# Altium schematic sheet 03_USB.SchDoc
size A2; ApprovedBy: DNP; CheckedBy: DNP; Author: DNP; CompanyName: Google LLC; DrawnBy: DNP; Engineer: Bangfei/Michael/Leo; Organization: Google LLC; Address1: 1600 Amphitheatre Parkway; Address2: Mountain View, CA 94043; Address3: DNP; Address4: DNP; DocumentNumber: DNP; Revision: PVT; SheetNumber: 3; SheetTotal: 11; VersionControl_RevNumber: DNP; IsUserConfigurable: DNP
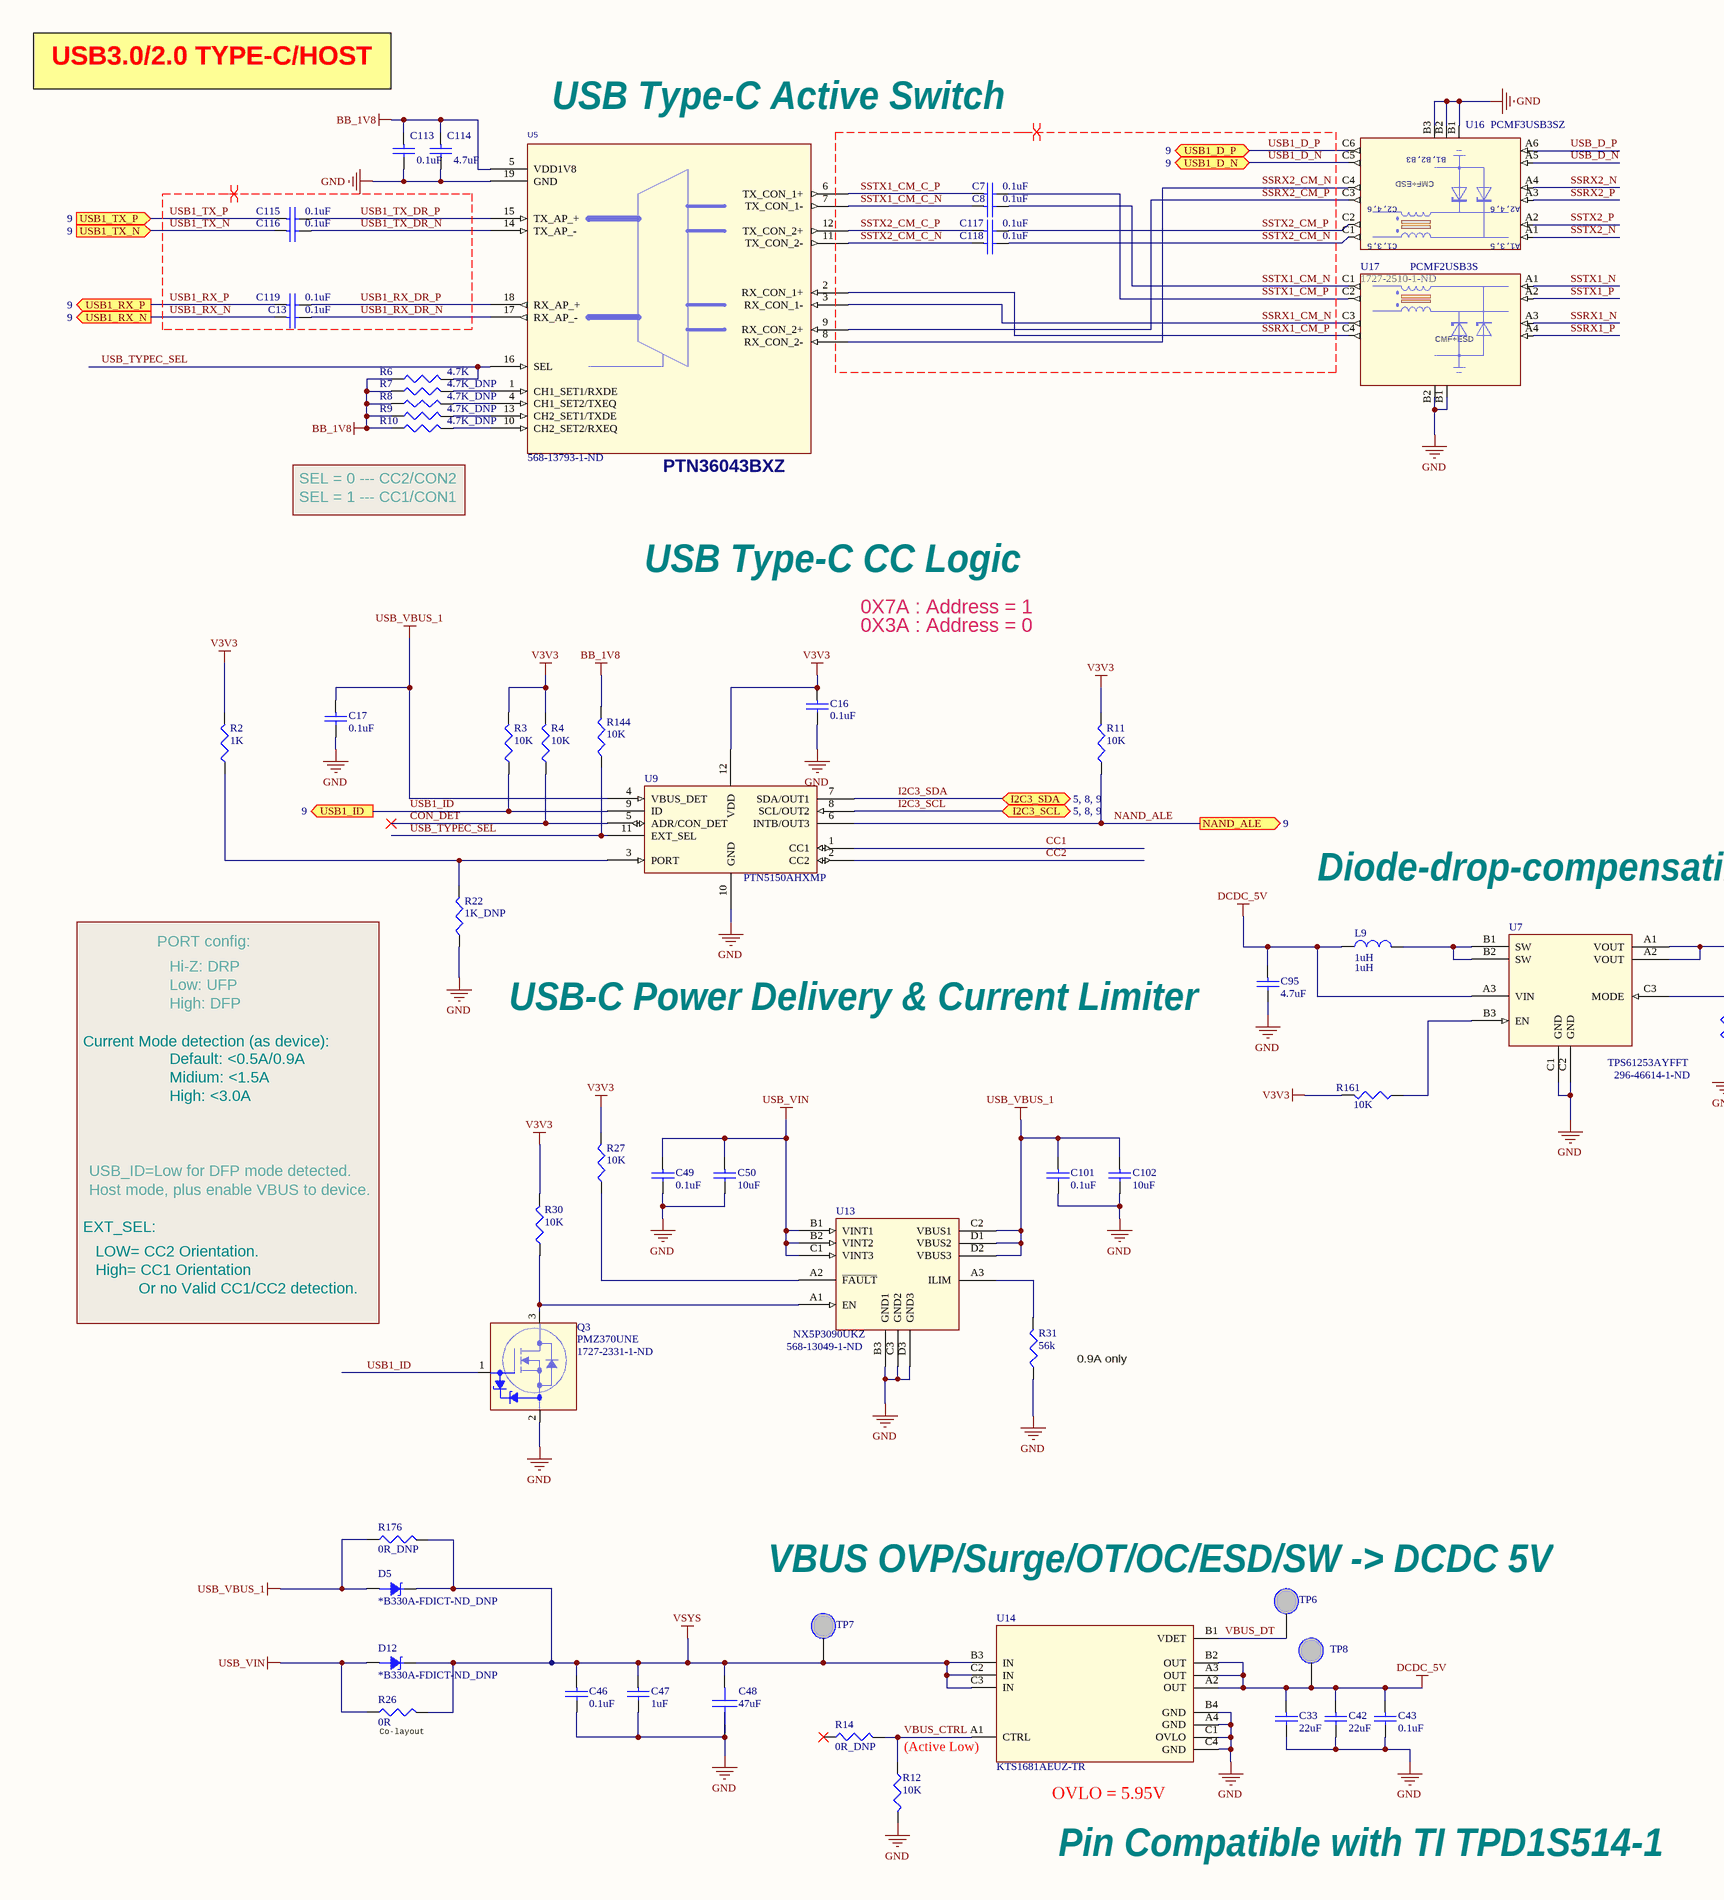
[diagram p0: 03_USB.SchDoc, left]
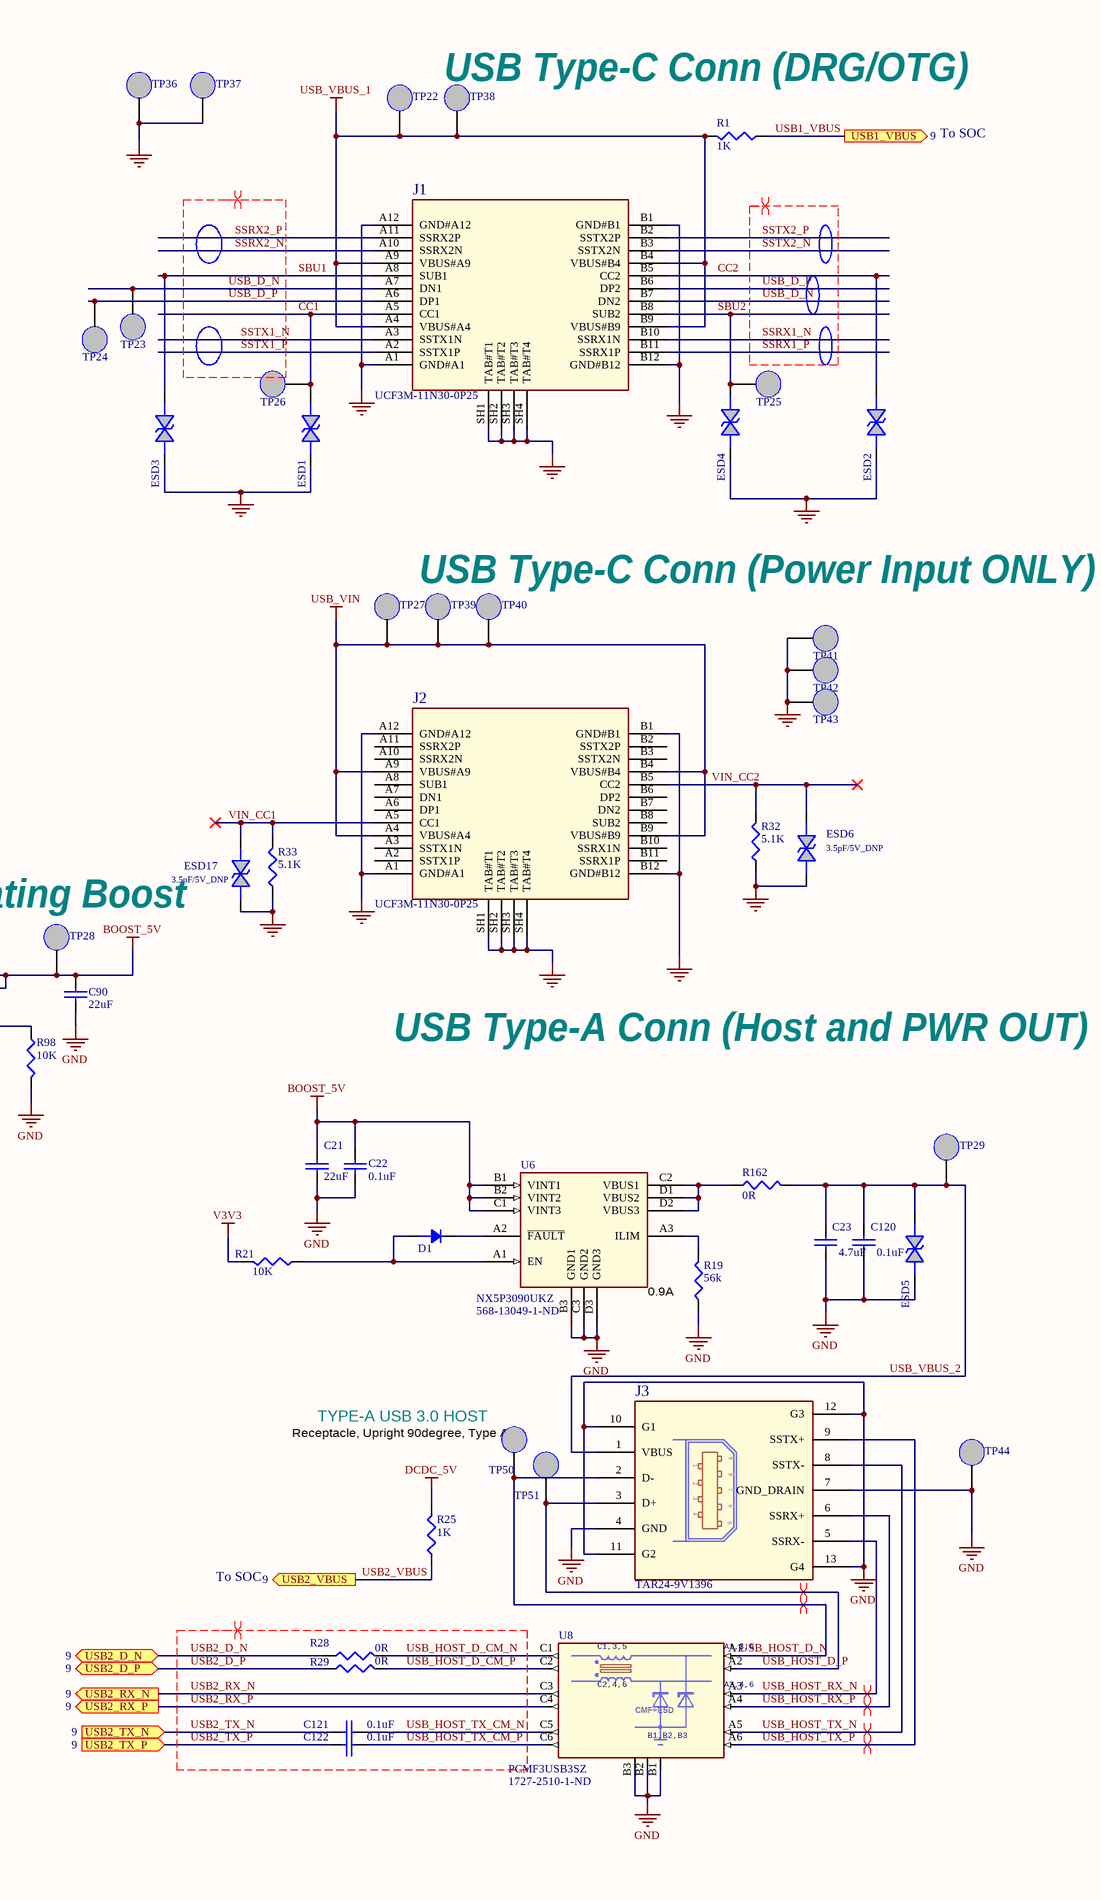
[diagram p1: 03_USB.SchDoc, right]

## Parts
C7  value 0.1uF  [0201]  (hidden comment: 0.1uF/10V)
C8  value 0.1uF  [0201]  (hidden comment: 0.1uF/10V)
C13  value 0.1uF  [0201]  (hidden comment: 0.1uF/10V)
C16  value 0.1uF  [0402]  (hidden comment: 0.1uF/25V)
C17  value 0.1uF  [0402]  (hidden comment: 0.1uF/25V)
C21  value 22uF  [0603]  (hidden comment: 22uF/10V)
C22  value 0.1uF  [0201]  (hidden comment: 0.1uF/10V)
C23  value 4.7uF  [0603]  (hidden comment: 4.7uF/10V)
C33  value 22uF  [0603]  (hidden comment: 22uF/10V)
C42  value 22uF  [0603]  (hidden comment: 22uF/10V)
C43  value 0.1uF  [0201]  (hidden comment: 0.1uF/10V)
C46  value 0.1uF  [0402]  (hidden comment: 0.1uF/25V)
C47  value 1uF  [0402]  (hidden comment: 1uF/25V)
C48  value 47uF  [1206]  (hidden comment: 47uF/25V)
C49  value 0.1uF  [0402]  (hidden comment: 0.1uF/25V)
C50  value 10uF  [0402]  (hidden comment: 10uF/10V)
C90  value 22uF  [0603]  (hidden comment: 10uF/10V)
C95  value 4.7uF  [0603]  (hidden comment: 4.7uF/10V)
C101  value 0.1uF  [0402]  (hidden comment: 0.1uF/25V)
C102  value 10uF  [0402]  (hidden comment: 10uF/10V)
C113  value 0.1uF  [0201]  (hidden comment: 0.1uF/10V)
C114  value 4.7uF  [0402]  (hidden comment: 4.7uF/10V)
C115  value 0.1uF  [0201]  (hidden comment: 0.1uF/10V)
C116  value 0.1uF  [0201]  (hidden comment: 0.1uF/10V)
C117  value 0.1uF  [0201]  (hidden comment: 0.1uF/10V)
C118  value 0.1uF  [0201]  (hidden comment: 0.1uF/10V)
C119  value 0.1uF  [0201]  (hidden comment: 0.1uF/10V)
C120  value 0.1uF  [0201]  (hidden comment: 0.1uF/10V)
C121  value 0.1uF  [0201]  (hidden comment: 0.1uF/10V)
C122  value 0.1uF  [0201]  (hidden comment: 0.1uF/10V)
D1  CUS10F30  [0805-Diode]  (value not drawn)
D5  Supplier Part Number 1: *B330A-FDICT-ND_DNP  [SMA-Diode]  (hidden comment: B330A-FDICT-ND_DNP)
D12  Supplier Part Number 1: *B330A-FDICT-ND_DNP  [SMA-Diode]  (hidden comment: B330A-FDICT-ND_DNP)
ESD1  3.5pF/5V  [0201]  (value not drawn)
ESD2  3.5pF/5V  [0201]  (value not drawn)
ESD3  3.5pF/5V  [0201]  (value not drawn)
ESD4  3.5pF/5V  [0201]  (value not drawn)
ESD5  3.5pF/5V  [0201]  (value not drawn)
ESD6  3.5pF/5V_DNP  [0201]
ESD17  3.5pF/5V_DNP  [0201]
J1  UCF3M-11N30-0P25  [USB12_0_5-UCF3M-11N30-0P25]
J2  UCF3M-11N30-0P25  [USB12_0_5-UCF3M-11N30-0P25]
J3  TAR24-9V1396  [USB9-3_0-TAR24-9V1396]
L9  1uH  [INDC2016X12L]
Q3  PMZ370UNE  Supplier Part Number 1: 1727-2331-1-ND  [DFN10106B]
R1  value 1K  [0201]  (hidden comment: 1K/1%)
R2  value 1K  [0201]  (hidden comment: 1K/1%)
R3  10K  [0201]
R4  10K  [0201]
R6  4.7K  [0201]
R7  value 4.7K_DNP  [0201]  (hidden comment: 4.7K)
R8  value 4.7K_DNP  [0201]  (hidden comment: 4.7K)
R9  value 4.7K_DNP  [0201]  (hidden comment: 4.7K)
R10  value 4.7K_DNP  [0201]  (hidden comment: 4.7K)
R11  10K  [0201]
R12  10K  [0201]
R14  0R_DNP  [0201]
R19  56k  [0402]
R21  10K  [0201]
R22  1K_DNP  [0201]
R25  value 1K  [0201]  (hidden comment: 1K/1%)
R26  0R  [1206]
R27  10K  [0201]
R28  0R  [0201]
R29  0R  [0201]
R30  10K  [0201]
R31  56k  [0402]
R32  5.1K  [0201]
R33  5.1K  [0201]
R98  10K  [0201]
R144  10K  [0201]
R161  10K  [0201]
R162  0R  [0402]
R176  value 0R_DNP  [1206]  (hidden comment: 0R)
TP6  TP NM  [TP_SMD_L]  (value not drawn)  (no BOM)
TP7  TP NM  [TP_SMD_L]  (value not drawn)  (no BOM)
TP8  TP NM  [TP_SMD_L]  (value not drawn)  (no BOM)
TP22  TP NM  [TP_SMD_L]  (value not drawn)  (no BOM)
TP23  TP NM  [TP_SMD]  (value not drawn)  (no BOM)
TP24  TP NM  [TP_SMD]  (value not drawn)  (no BOM)
TP25  TP NM  [TP_SMD]  (value not drawn)  (no BOM)
TP26  TP NM  [TP_SMD]  (value not drawn)  (no BOM)
TP27  TP NM  [TP_SMD_L]  (value not drawn)  (no BOM)
TP28  TP NM  [TP_SMD_L]  (value not drawn)  (no BOM)
TP29  TP NM  [TP_SMD_L]  (value not drawn)  (no BOM)
TP36  TP NM  [TP_SMD_L]  (value not drawn)  (no BOM)
TP37  TP NM  [TP_SMD_L]  (value not drawn)  (no BOM)
TP38  TP NM  [TP_SMD_L]  (value not drawn)  (no BOM)
TP39  TP NM  [TP_SMD_L]  (value not drawn)  (no BOM)
TP40  TP NM  [TP_SMD_L]  (value not drawn)  (no BOM)
TP41  TP NM  [TP_SMD_L]  (value not drawn)  (no BOM)
TP42  TP NM  [TP_SMD_L]  (value not drawn)  (no BOM)
TP43  TP NM  [TP_SMD_L]  (value not drawn)  (no BOM)
TP44  TP NM  [TP_SMD_L]  (value not drawn)  (no BOM)
TP50  TP NM  [TP_SMD_L]  (value not drawn)  (no BOM)
TP51  TP NM  [TP_SMD_L]  (value not drawn)  (no BOM)
U5  PTN36043BXZ  Supplier Part Number 1: 568-13793-1-ND  [DHXQFN18_0P4_2X2P45]
U6  NX5P3090UKZ  Supplier Part Number 1: 568-13049-1-ND  [WLCSP12_0P4_1P38X1P68MM_SMDP]
U7  TPS61253AYFFT  Supplier Part Number 1: 296-46614-1-ND  [WLCSP_BGA3x3]
U8  PCMF3USB3SZ  Supplier Part Number 1: 1727-2510-1-ND  [WLCSP15_0P4_2P42X1P22_SMDP]
U9  PTN5150AHXMP  [X2QFN12_0P4_1P6X1P6]
U13  NX5P3090UKZ  Supplier Part Number 1: 568-13049-1-ND  [WLCSP12_0P4_1P38X1P68MM_SMDP]
U14  KTS1681AEUZ-TR  [WLCSP_BGA3x4]
U16  PCMF3USB3SZ  Supplier Part Number 1: 1727-2510-1-ND  [WLCSP15_0P4_2P42X1P22_SMDP]
U17  PCMF2USB3S  [WLCSP10_0P4_1P2X1P6MM_SMDP]

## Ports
I2C3_SCL (bidir, see 5, 8, 9), I2C3_SDA (bidir, see 5, 8, 9), NAND_ALE (out, see 9), USB1_D_N (bidir, see 9), USB1_D_P (bidir, see 9), USB1_ID (out, see 9), USB1_RX_N (out, see 9), USB1_RX_P (out, see 9), USB1_TX_N (in, see 9), USB1_TX_P (in, see 9), USB1_VBUS (out, see 9), USB2_D_N (bidir, see 9), USB2_D_P (bidir, see 9), USB2_RX_N (out, see 9), USB2_RX_P (out, see 9), USB2_TX_N (in, see 9), USB2_TX_P (in, see 9), USB2_VBUS (out, see 9)

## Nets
BB_1V8: C113.1 C114.1 R6.1 R7.1 R8.1 R9.1 R10.1 R144.2 U5.5(VDD1V8)
BOOST_5V: C21.1 C22.1 C90.1 TP28.1 U6.B1(VINT1) U6.B2(VINT2) U6.C1(VINT3) U7.A1(VOUT) U7.A2(VOUT)
DCDC_5V: C33.1 C42.1 C43.1 C95.1 L9.1 R25.2 TP8.1 U7.A3(VIN) U14.A2(OUT) U14.A3(OUT) U14.B2(OUT)
GND: C16.2 C17.2 C21.2 C22.2 C23.2 C33.2 C42.2 C43.2 C46.2 C47.2 C48.2 C49.2 C50.2 C90.2 C95.2 C101.2 C102.2 C113.2 C114.2 C120.2 ESD1.1 ESD2.1 ESD3.1 ESD4.1 ESD5.1 ESD6.1 ESD17.1 J1.A1(GND#A1) J1.A12(GND#A12) J1.B1(GND#B1) J1.B12(GND#B12) J1.SH1(TAB#T1) J1.SH2(TAB#T2) J1.SH3(TAB#T3) J1.SH4(TAB#T4) J2.A1(GND#A1) J2.A12(GND#A12) J2.B1(GND#B1) J2.B12(GND#B12) J2.SH1(TAB#T1) J2.SH2(TAB#T2) J2.SH3(TAB#T3) J2.SH4(TAB#T4) J3.4(GND) J3.7(GND_DRAIN) J3.10(G1) J3.11(G2) J3.12(G3) J3.13(G4) Q3.2(SOURCE) R12.2 R19.1 R22.1 R31.1 R32.1 R33.1 R98.2 TP36.1 TP37.1 TP41.1 TP42.1 TP43.1 TP44.1 U5.19(GND) U6.B3(GND1) U6.C3(GND2) U6.D3(GND3) U7.C1(GND) U7.C2(GND) U8.B1(GND_CH1) U8.B2(GND_CH2) U8.B3(GND_CH3) U9.10(GND) U13.B3(GND1) U13.C3(GND2) U13.D3(GND3) U14.A4(GND) U14.B4(GND) U14.C1(OVLO) U14.C4(GND) U16.B1(GND_CH1) U16.B2(GND_CH2) U16.B3(GND_CH3) U17.B1(GND_CH1) U17.B2(GND_CH2)
USB_VBUS_1: C17.1 C101.1 C102.1 D5.A J1.A4(VBUS#A4) J1.A9(VBUS#A9) J1.B4(VBUS#B4) J1.B9(VBUS#B9) R1.2 R176.1 TP22.1 TP38.1 U9.4(VBUS_DET) U13.C2(VBUS1) U13.D1(VBUS2) U13.D2(VBUS3)
USB_VIN: C49.1 C50.1 D12.A J2.A4(VBUS#A4) J2.A9(VBUS#A9) J2.B4(VBUS#B4) J2.B9(VBUS#B9) R26.1 TP27.1 TP39.1 TP40.1 U13.B1(VINT1) U13.B2(VINT2) U13.C1(VINT3)
V3V3: C16.1 R2.2 R3.2 R4.2 R11.2 R21.2 R27.2 R30.2 R161.2 U9.12(VDD)
VSYS: C46.1 C47.1 C48.1 D5.C D12.C R26.2 R176.2 TP7.1 U14.B3(IN) U14.C2(IN) U14.C3(IN)
CC1: ESD1.2 J1.A5(CC1) TP26.1 U9.1(CC1)
CC2: ESD2.2 J1.B5(CC2) U9.2(CC2)
CON_DET: R4.1 U9.5(ADR/CON_DET)
I2C3_SCL: U9.8(SCL/OUT2) ; port I2C3_SCL
I2C3_SDA: U9.7(SDA/OUT1) ; port I2C3_SDA
NAND_ALE: R11.1 U9.6(INTB/OUT3) ; port NAND_ALE
SBU1: ESD3.2 J1.A8(SUB1)
SBU2: ESD4.2 J1.B8(SUB2) TP25.1
SSRX1_CM_N: U5.3(RX_CON_1-) U17.C3(CH2_OUT+)
SSRX1_CM_P: U5.2(RX_CON_1+) U17.C4(CH2_OUT-)
SSRX1_N: J1.B10(SSRX1N) U17.A3(CH2_IN+)
SSRX1_P: J1.B11(SSRX1P) U17.A4(CH2_IN-)
SSRX2_CM_N: U5.8(RX_CON_2-) U16.C4(CH2_OUT-)
SSRX2_CM_P: U5.9(RX_CON_2+) U16.C3(CH2_OUT+)
SSRX2_N: J1.A10(SSRX2N) U16.A4(CH2_IN-)
SSRX2_P: J1.A11(SSRX2P) U16.A3(CH2_IN+)
SSTX1_CM_C_N: C8.1 U5.7(TX_CON_1-)
SSTX1_CM_C_P: C7.1 U5.6(TX_CON_1+)
SSTX1_CM_N: C8.2 U17.C1(CH1_OUT+)
SSTX1_CM_P: C7.2 U17.C2(CH1_OUT-)
SSTX1_N: J1.A3(SSTX1N) U17.A1(CH1_IN+)
SSTX1_P: J1.A2(SSTX1P) U17.A2(CH1_IN-)
SSTX2_CM_C_N: C118.1 U5.11(TX_CON_2-)
SSTX2_CM_C_P: C117.1 U5.12(TX_CON_2+)
SSTX2_CM_N: C118.2 U16.C1(CH1_OUT+)
SSTX2_CM_P: C117.2 U16.C2(CH1_OUT-)
SSTX2_N: J1.B3(SSTX2N) U16.A1(CH1_IN+)
SSTX2_P: J1.B2(SSTX2P) U16.A2(CH1_IN-)
USB1_D_N: U16.C5(CH3_OUT+) ; port USB1_D_N
USB1_D_P: U16.C6(CH3_OUT-) ; port USB1_D_P
USB1_ID: Q3.1(GATE) R3.1 U9.9(ID) ; port USB1_ID
USB1_RX_DR_N: C13.2 U5.17(RX_AP_-)
USB1_RX_DR_P: C119.2 U5.18(RX_AP_+)
USB1_RX_N: C13.1 ; port USB1_RX_N
USB1_RX_P: C119.1 ; port USB1_RX_P
USB1_TX_DR_N: C116.2 U5.14(TX_AP_-)
USB1_TX_DR_P: C115.2 U5.15(TX_AP_+)
USB1_TX_N: C116.1 ; port USB1_TX_N
USB1_TX_P: C115.1 ; port USB1_TX_P
USB1_VBUS: R1.1 ; port USB1_VBUS
USB2_D_N: R28.1 ; port USB2_D_N
USB2_D_P: R29.1 ; port USB2_D_P
USB2_RX_N: U8.C3(CH2_OUT+) ; port USB2_RX_N
USB2_RX_P: U8.C4(CH2_OUT-) ; port USB2_RX_P
USB2_TX_N: C121.1 ; port USB2_TX_N
USB2_TX_P: C122.1 ; port USB2_TX_P
USB2_VBUS: R25.1 ; port USB2_VBUS
USB_D_N: J1.A7(DN1) J1.B7(DN2) TP23.1 U16.A5(CH3_IN+)
USB_D_P: J1.A6(DP1) J1.B6(DP2) TP24.1 U16.A6(CH3_IN-)
USB_HOST_D_CM_N: R28.2 U8.C1(CH1_OUT+)
USB_HOST_D_CM_P: R29.2 U8.C2(CH1_OUT-)
USB_HOST_D_N: J3.2(D-) TP50.1 U8.A1(CH1_IN+)
USB_HOST_D_P: J3.3(D+) TP51.1 U8.A2(CH1_IN-)
USB_HOST_RX_N: J3.5(SSRX-) U8.A3(CH2_IN+)
USB_HOST_RX_P: J3.6(SSRX+) U8.A4(CH2_IN-)
USB_HOST_TX_CM_N: C121.2 U8.C5(CH3_OUT+)
USB_HOST_TX_CM_P: C122.2 U8.C6(CH3_OUT-)
USB_HOST_TX_N: J3.8(SSTX-) U8.A5(CH3_IN+)
USB_HOST_TX_P: J3.9(SSTX+) U8.A6(CH3_IN-)
USB_TYPEC_SEL: R6.2 R144.1 U5.16(SEL) U9.11(EXT_SEL)
USB_VBUS_2: C23.1 C120.1 ESD5.2 J3.1(VBUS) R162.2 TP29.1
VBUS_CTRL: R12.1 R14.2 U14.A1(CTRL)
VBUS_DT: TP6.1 U14.B1(VDET)
VIN_CC1: ESD17.2 J2.A5(CC1) R33.2
VIN_CC2: ESD6.2 J2.B5(CC2) R32.2
NetD1_A: D1.A R21.1 U6.A1(EN)
NetD1_K: D1.K U6.A2(~{FAULT})
NetL9_2: L9.2 U7.B1(SW) U7.B2(SW)
NetQ3_3: Q3.3(DRAIN) R30.1 U13.A1(EN)
NetR2_1: R2.1 R22.2 U9.3(PORT)
NetR7_2: R7.2 U5.1(CH1_SET1/RXDE)
NetR8_2: R8.2 U5.4(CH1_SET2/TXEQ)
NetR9_2: R9.2 U5.13(CH2_SET1/TXDE)
NetR10_2: R10.2 U5.10(CH2_SET2/RXEQ)
NetR19_2: R19.2 U6.A3(ILIM)
NetR27_1: R27.1 U13.A2(~{FAULT})
NetR31_2: R31.2 U13.A3(ILIM)
NetR98_1: R98.1 U7.C3(MODE)
NetR161_1: R161.1 U7.B3(EN)
NetR162_1: R162.1 U6.C2(VBUS1) U6.D1(VBUS2) U6.D2(VBUS3)

Not connected (* = marked no-connect by the designer): J2 A2(SSTX1P) A3(SSTX1N) A6(DP1) A7(DN1) A8(SUB1) A10(SSRX2N) A11(SSRX2P) B2(SSTX2P) B3(SSTX2N) B6(DP2) B7(DN2) B8(SUB2) B10(SSRX1N) B11(SSRX1P); R14 1*

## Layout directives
differential pair: SSRX1_CM_N, SSRX1_CM_P, SSRX1_N, SSRX1_P, SSRX2_CM_N, SSRX2_CM_P, SSRX2_N, SSRX2_P, SSTX1_CM_C_N, SSTX1_CM_C_P, SSTX1_CM_N, SSTX1_CM_P, SSTX1_N, SSTX1_P, SSTX2_CM_C_N, SSTX2_CM_C_P, SSTX2_CM_N, SSTX2_CM_P, SSTX2_N, SSTX2_P, USB1_D_N, USB1_D_P, USB1_RX_DR_N, USB1_RX_DR_P, USB1_RX_N, USB1_RX_P, USB1_TX_DR_N, USB1_TX_DR_P, USB1_TX_N, USB1_TX_P, USB2_D_N, USB2_D_P, USB2_RX_N, USB2_RX_P, USB2_TX_N, USB2_TX_P, USB_D_N, USB_D_P, USB_HOST_D_CM_N, USB_HOST_D_CM_P, USB_HOST_D_N, USB_HOST_D_P, USB_HOST_RX_N, USB_HOST_RX_P, USB_HOST_TX_CM_N, USB_HOST_TX_CM_P, USB_HOST_TX_N, USB_HOST_TX_P

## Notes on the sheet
- USB3.0/2.0 TYPE-C/HOST
- (near TP38) USB Type-C Conn (DRG/OTG)
- USB Type-C Active Switch
- To SOC
- SEL = 0 --- CC2/CON2
- SEL = 1 --- CC1/CON1
- USB Type-C CC Logic
- USB Type-C Conn (Power Input ONLY)
- 0X7A : Address = 1
- 0X3A : Address = 0
- Diode-drop-compensating Boost
- PORT config:
- Hi-Z: DRP
- Low: UFP
- High: DFP
- (near C95) USB-C Power Delivery & Current Limiter
- USB Type-A Conn (Host and PWR OUT)
- Current Mode detection (as device):
- Default: <0.5A/0.9A
- Midium: <1.5A
- High: <3.0A
- USB_ID=Low for DFP mode detected.
- Host mode, plus enable VBUS to device.
- EXT_SEL:
- LOW= CC2 Orientation.
- High= CC1 Orientation
- (near U6) 0.9A
- Or no Valid CC1/CC2 detection.
- (near R31) 0.9A only
- TYPE-A USB 3.0 HOST
- (near TP50) Receptacle, Upright 90degree, Type A
- (near TP6) VBUS OVP/Surge/OT/OC/ESD/SW -> DCDC 5V
- (near R26) Co-layout
- (Active Low)
- (near U14) OVLO = 5.95V
- Pin Compatible with TI TPD1S514-1

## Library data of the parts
C7 C8 C13 C113 C115-C119 = CAP_0201_0.1uF: CAP CER 0.1UF 10V 10% X5R 0201; MPN: C0603X5R1A104K030BC; QCI MPN: GRM033R61A104K; QPN: CH4102K9E00; QPN Description: CAP CHIP 0.1U 10V(+-10%,X5R,0201); Function Code: HUB
C16 C17 = CAP_0402_0.1uF_25V: CAP CER 0.1uF 25V 10% X7R 0402; MPN: TMK105BJ104KV-F; QCI MPN: GRM155R71E104K; QPN: CH4104K1B00; QPN Description: CAP CHIP 0.1U 25V(+-10%,X7R,0402); Function Code: HUB
C21 C33 C42 = CAP_0603_22uF: CAP CER 22UF 6.3V 10% X5R 0603; MPN: CL10A226KQ8NRNE; QCI MPN: GRM188R61A226M; QPN: CH6222M9901; QPN Description: CAP CHIP 22UF 10V(+-20%,X5R,0603); Function Code: USB
C22 C43 C120-C122 = CAP_0201_0.1uF: CAP CER 0.1UF 10V 10% X5R 0201; MPN: C0603X5R1A104K030BC; QCI MPN: GRM033R61A104K; QPN: CH4102K9E00; QPN Description: CAP CHIP 0.1U 10V(+-10%,X5R,0201); Function Code: USB
C23 = CAP_0603_4.7uF: CAP CER 4.7uF 10V 10% X5R 0603; MPN: CGB3B1X5R1A475K055AC; QCI MPN: GRM188C71A475K; QPN: CH5472M6900; QPN Description: CAP CHIP 4.7UF 10V(+-10%,X7S,0603); Function Code: USB
C46 C49 C101 = CAP_0402_0.1uF_25V: CAP CER 0.1uF 25V 10% X7R 0402; MPN: TMK105BJ104KV-F; QCI MPN: GRM155R71E104K; QPN: CH4104K1B00; QPN Description: CAP CHIP 0.1U 25V(+-10%,X7R,0402); Function Code: USB
C47 = CAP_0402_1.0uF_25V: CAP CER 1.0UF 25V 10% X5R 0402; MPN: TMK105BJ105MV-F; QCI MPN: GRM155R61E105K; QPN: CH5104K9B01; QPN Description: CAP CHIP 1UF 25V(+-10%,X5R,0402); Function Code: USB
C48 = CAP_1206_47uF_25V: CAP CER 47UF 25V 20% 1206; MPN: C3216JB1E476M160AC; Function Code: USB
C50 C102 = CAP_0603_4.7uF_35V: CAP CER 10UF 10V 20% X5R 0402; MPN: CL05A106MP5NUNC; QCI MPN: GRM155R61A106M; QPN: CH6102M9B00; QPN Description: CAP CHIP 10U 10V (+-20%, X5R, 0402)'; Function Code: USB
C90 = CAP_0603_22uF: CAP CER 22UF 6.3V 10% X5R 0603; MPN: CL10A226KQ8NRNE; QCI MPN: GRM188R61A106M; QPN: CH6102M9900; QPN Description: CAP CHIP 10U 10V(+-20%,X5R,0603); Function Code: USB
C95 = CAP_0603_4.7uF: CAP CER 4.7uF 10V 10% X5R 0603; MPN: CGB3B1X5R1A475K055AC; QCI MPN: GRM188C71A475K; QPN: CH5472M6900; QPN Description: CAP CHIP 4.7UF 10V(+-10%,X7S,0603); Function Code: DCD
C114 = CAP_0402_4.7uF: CAP CER 4.7UF 10V 20% X5R 0402; MPN: C1005X5R1A475M050BC; QCI MPN: GRM155R61A475M; QPN: CH5472M9B01; QPN Description: CAP CHIP 4.7U 10V(+-20%,X5R,0402); Function Code: HUB
D1 = Diode_Schottky_0805: DIODE SCHOTTKY 20V 1A 0805; Function Code: USB; QPN: BC0CUS10000; QPN Description: DIODE SMD SCHOTTKY  CUS10F30(30V,1A)
D5 D12 = Diode_Schottky_B330A-13-F: Function Code: USB; DNP: V
ESD1-ESD5 = DIODE BI-DIR TRIG: DIODE TVS 15kV 10V 50A 8pF SMT RoHS; MPN: DESD5V0V1BCSP-7; QPN: BC5V0V1BZ02; QPN Description: DIODE ESD SMD DESD5V0V1BCSP-7 6V,DSN0603; Function Code: USB
ESD6 ESD17 = DIODE BI-DIR TRIG: DIODE TVS 15kV 10V 50A 8pF SMT RoHS; MPN: DESD5V0V1BCSP-7; QPN: BC5V0V1BZ02; QPN Description: DIODE ESD SMD DESD5V0V1BCSP-7 6V,DSN0603; Function Code: USB; DNP: V
J1 J2 = CONN_USBC_RCPT_UCF3M-11N30-0P25: QPN: DFHS24FR262; QPN Description: CONN SMD USB3.1C 24P 2R FR(P0.5,H2.38); Function Code: USB
J3 = CONN_USBA_ACON_TAR24-9V1396: CONN, USB TYPE A, 3.0 REC TH; QPN: DFHS09FR696; QPN Description: CONN DIP USB3.0 9P 2R FR(P1.0,H5.76)
L9 = INDUCTOR_VLS201612HBX-1R0M-1: FIXED IND 1UH 2.7A 72 MOHM SMD; QPN: TV-1024MZ03; QPN Description: IND SMD 1U 20% 2.42A VLS201612HBX E-SEL; Function Code: DCD
Q3 = NMOS_NX3008NBK: N-Channel 30V 590mA, SMT DFN1006B-3; MPN: PMZB550UNEYL; Function Code: USB; QPN: BAM03700000; QPN Description: TRANS MOSFET PMZ370UNE (30V,0.9 A,0.36W)
R1 R25 = R_0201_1K: RES SMD 1K OHM 1% 1/20W 0201; MPN: ERJ-1GEF1001C; QCI MPN: RC0201FR-131KL; QPN: CS21001FE04; QPN Description: RES CHIP 1K 1/20W +-1%(0201); Function Code: USB
R2 = R_0201_1K: RES SMD 1K OHM 1% 1/20W 0201; MPN: ERJ-1GEF1001C; QCI MPN: RC0201FR-131KL; QPN: CS21001FE04; QPN Description: RES CHIP 1K 1/20W +-1%(0201); Function Code: HUB
R3 R4 R11 R144 = R_0201_10K: RES SMD 10K OHM JUMPER 1/20W  0201; MPN: ERJ-1GEF103C; QCI MPN: RC0201JR-1310KL; QPN: CS31001JE16; QPN Description: RES CHIP 10K 1/20W +-5%(0201); Function Code: HUB
R6-R10 = R_0201_4.7K: RES SMD 4.7K OHM 1% 1/20W 0201; MPN: ERJ-1GEF4701C; QCI MPN: RC0201FR-134K7L; QPN: CS24701FE00; QPN Description: RES CHIP 4.7K 1/20W +-1%(0201; Function Code: HUB
R12 R21 R27 R30 = R_0201_10K: RES SMD 10K OHM JUMPER 1/20W  0201; MPN: ERJ-1GEF103C; QCI MPN: RC0201JR-1310KL; QPN: CS31001JE16; QPN Description: RES CHIP 10K 1/20W +-5%(0201); Function Code: USB
R14 = R_0201_0: RES SMD 0.0OHM JUMPER 1/20W 0201; MPN: ERJ-1GN0R00C; QCI MPN: RC0201JR-130RL; DNP: V; QPN: CS00001JE18; QPN Description: RES CHIP 0(1/20W,+-5%,0201); Function Code: USB
R19 R31 = R_0402_56k: RES SMD 56K OHM 1% 1/10W 0402; MPN: ERJ-2RKF5602X; QCI MPN: RC0402FR-0756K; QPN: CS35602FB02; QPN Description: RES CHIP 56K 1/16W +-1%(0402); Function Code: USB
R22 = R_0201_1K: RES SMD 1K OHM 1% 1/20W 0201; MPN: ERJ-1GEF1001C; QCI MPN: RC0201FR-131KL; DNP: V; QPN: CS21001FE04; QPN Description: RES CHIP 1K 1/20W +-1%(0201); Function Code: HUB
R26 R176 = R_1206_0: RES SMD 0.0 OHM JUMPER 1/4W 1206; MPN: RC1206JR-070RL; QPN: CS00006J248; QPN Description: RES CHIP 0 1/4W +-5%(1206); Function Code: USB
R28 R29 = R_0201_0: RES SMD 0.0OHM JUMPER 1/20W 0201; MPN: ERJ-1GN0R00C; QCI MPN: RC0201JR-130RL; QPN: CS00001JE18; QPN Description: RES CHIP 0(1/20W,+-5%,0201); Function Code: USB
R32 R33 = R_0201_5.1K: RES SMD 5.1K OHM JUMPER 1/20W  0201; MPN: ERJ-JGEF5101C; QCI MPN: RC0201FR-075K1L; QPN: CS25101FE00; QPN Description: RES CHIP 5.1K 1/20W +-1%(0201); Function Code: USB
R98 R161 = R_0201_10K: RES SMD 10K OHM JUMPER 1/20W  0201; MPN: ERJ-1GEF103C; QCI MPN: RC0201JR-1310KL; QPN: CS31001JE16; QPN Description: RES CHIP 10K 1/20W +-5%(0201); Function Code: DCD
R162 = R_0402_0: RES SMD 0.0 OHM JUMPER 1/10W  0402; MPN: ERJ-2GE0R00X; QCI MPN: RC0402FR-070RL; QPN: CS00002FB00; QPN Description: RES CHIP 0 1/16W +-1%(0402); Function Code: USB
TP6-TP8 TP22 TP27-TP29 TP36-TP44 TP50 TP51 = TP_L: TEST POINT (Large)
TP23-TP26 = TP: TEST POIN
U5 = PTN36043BX_DHXQFN18_23: IC USB TYPE-C SS ACTIVE DEMUX 1.8V DHXQFN18; QCI MPN: PTN36043BXY; Function Code: HUB; QPN: AL036043000; QPN Description: IC OTHER(18P)PTN36043BXY(DHX2QFN18)
U6 U13 = NX5P3090UKZ_WLCSP12: Function Code: USB; QPN: AL003090U00; QPN Description: IC OTHER(12P) NX5P3090UK (WLCSP)
U7 = TPS61253A: QCI MPN: TPS61253AYFFR; Function Code: DCD; QPN: AL061253T00; QPN Description: IC OTHER(9P)TPS61253AYFFR(DSBGA)
U8 = PCMF3USB3S_A: Function Code: USB; QPN: CX3USB3S000; QPN Description: EMI FILTER PCMF3USB3S(3,100NA)
U9 = PTN5150A_X2QFN12: QPN: AL005150000; QPN Description: IC OTHER(12P)PTN5150AHXMP(X2QFN12); Function Code: HUB
U14 = KTS1681A: USB Over Voltage, SUrge and ESD protection for VBUS, WCSP12; QPN: AL001681U00; QPN Description: IC OTHER(12P) KTS1681AEUZ-TR (WLCSP)
U16 = PCMF3USB3S_A: Function Code: HUB; QPN: CX3USB3S000; QPN Description: EMI FILTER PCMF3USB3S(3,100NA)
U17 = PCMF2USB3S_10P: QPN: CX2USB3S000; QPN Description: EMI FILTER PCMF2USB3S(3,100NA); Function Code: HUB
